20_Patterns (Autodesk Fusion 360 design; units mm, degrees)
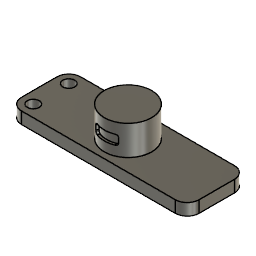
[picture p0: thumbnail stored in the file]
part number: 2026-07-16-13-26-31-197
sketch "Sketch1" plane through (0, 0, 0) normal (0, 0, 1) x axis (1, 0, 0)
  line L1 (-75, -25) -> (75, -25)
  line L2 (-75, 25) -> (-75, -25)
  line L3 (75, 25) -> (-75, 25)
  line L4 (75, -25) -> (75, 25)
  line L5 (-75, 25) -> (75, -25)
  line L6 (75, 25) -> (-75, -25)
  point P6 (0, 0)
  point P1 (0, 0)
  point P4 (-75, 25)
  point P5 (75, 25)
  point P3 (-75, -25)
  horizontal L1
  perpendicular L1 L2
  parallel L1 L3
  parallel L2 L4
  coincident L5 P6
  coincident L6 P6
  coincident P1 P6
  dimension "d1" distance P4 P5 = 150
  dimension "d2" distance P3 P4 = 50
extrude "Extrude1" new body sketch "Sketch1" profile of L1 L2 L3 L4 along normal blind 10
sketch "Sketch2" plane through (0, 0, 10) normal (0, 0, 1) x axis (-1, 0, 0)
  line L1 (75, -25) -> (-75, -25)
  line L2 (75, 25) -> (75, -25)
  line L3 (-75, 25) -> (75, 25)
  line L4 (-75, -25) -> (-75, 25)
  circle C1 centre (0, 0) radius 20
  point P1 (0, 0)
  point P6 (0, 0)
  coincident P1 P6
  dimension "d5" diameter C1 = 40
extrude "Extrude2" add sketch "Sketch2" profile of C1 along normal blind 25
sketch "Sketch3" plane through (0, -25, 0) normal (0, -1, 0) x axis (1, 0, 0)
  line L1 (75, 0) -> (-75, 0)
  line L2 (75, 10) -> (75, 0)
  line L3 (-75, 10) -> (75, 10)
  line L4 (-75, 0) -> (-75, 10)
  line L5 (-10, 18) -> (10, 18)
  line L6 (-10, 26) -> (-10, 18)
  line L7 (10, 26) -> (-10, 26)
  line L8 (10, 18) -> (10, 26)
  line L9 (-10, 26) -> (10, 18)
  line L10 (10, 26) -> (-10, 18)
  point P10 (0, 22)
  point P8 (-10, 26)
  point P9 (10, 26)
  point P7 (-10, 18)
  point P1 (0, 0)
  horizontal L5
  perpendicular L5 L6
  parallel L5 L7
  parallel L6 L8
  coincident L9 P10
  coincident L10 P10
  dimension "d8" distance P8 P9 = 20
  dimension "d9" distance P7 P8 = 8
  dimension "d10" distance P1 P10 = 22
emboss "Emboss1" sketch "Sketch3" Depth -2 Horizontal Distance 0 Vertical Distance 0 Rotation Angle 0
fillet "Fillet1" radius 2
fillet "Fillet2" radius 10
hole "Hole1" HoleDiameter 10 TipAngle 118
hole "Hole2" HoleDepth 10 HoleDiameter 10 TipAngle 118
